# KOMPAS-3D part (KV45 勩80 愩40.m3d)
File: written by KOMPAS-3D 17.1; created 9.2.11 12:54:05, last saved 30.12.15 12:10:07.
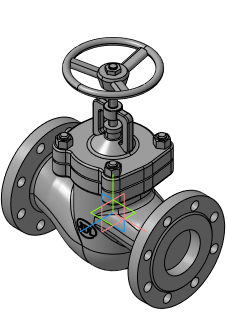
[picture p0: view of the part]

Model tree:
1. Плоскость XY
2. Плоскость ZX
3. Плоскость ZY
4. Ось X
5. Ось Y
6. Ось Z
7. Начало координат
8. Операция без истории:4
